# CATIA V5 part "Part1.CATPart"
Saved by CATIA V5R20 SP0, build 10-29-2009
Part number: 饮料瓶
Material "Gravel 1": density 2250 kg/m3, Young's modulus 5e+10 Pa, Poisson ratio 0.25
Bounding box of the stored display mesh (mm): x -25 to 26, y -25 to 180.655, z 0 to 110
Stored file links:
  C:\Users\DELL\Desktop\饮料瓶\Part1.CATPart
  C:\Program Files (x86)\Dassault Systemes\B20\intel_a\startup\materials\Catalog.CATMaterial
  C:\Program Files (x86)\Dassault Systemes\B20\intel_a\startup\materials\kitchen_floor.jpg
  C:\Program Files (x86)\Dassault Systemes\B20\intel_a\startup\materials\gravel_1.jpg
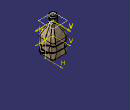
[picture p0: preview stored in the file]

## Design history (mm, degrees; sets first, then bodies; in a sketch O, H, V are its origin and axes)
Set1
  Sketch1 on xy-plane, origin (0, 0, 0), H (1, 0, 0), V (0, 1, 0)
    line L1 (25, 25) -> (25, -25)
    line L2 (25, -25) -> (-25, -25)
    line L3 (-25, -25) -> (-25, 25)
    line L4 (-25, 25) -> (25, 25)
    length L1 = 50
    length L2 = 50
    vertical: L1 V, L3 V
    horizontal: L2 H, L4 H
    equidistance: L1 L3 O, L2 L4 O
  Sketch2 on face of Pad1 from Sketch1.L3, origin (-25, 0, 0), H (0, -1, 0), V (0, 0, 1)
    spline S1 through (-40, 10) (-10, 20) (20, 10) (30, 20) (40, 30)
  Extrude1: Element1 Sketch2, Lim1 80, Lim2 80
  MultiSel1: CommonCtxFeats ({extract ExtractElem face of Pad1 from Sketch1.L3}; {extract ExtractElem face of Fillet1}; {extract ExtractElem face of Pad1 from Sketch1.L2}; {extract ExtractElem face of Fillet1}; {extract ExtractElem face of Pad1 from Sketch1.L1}; {extract ExtractElem face of Fillet1}; {extract ExtractElem face of Pad1 from Sketch1.L4}; {extract ExtractElem face of Fillet1})
  Sketch3 on face of Pad1 from Sketch1.L2, origin (0, -25, 0), H (1, 0, 0), V (0, 0, 1)
    spline S1 through (-30, 30) (-10, 40) (20, 30) (40, 40)
  Extrude2: Element1 Sketch3, Lim1 80, Lim2 80
  Sketch4 on face of Pad1 from Sketch1.L3, origin (-25, 0, 0), H (0, -1, 0), V (0, 0, 1)
    spline S1 through (-40, 30) (-10, 40) (10, 30) (50, 40)
  Extrude3: Element1 Sketch4, Lim1 80, Lim2 80
  MultiSel2: CommonCtxFeats ({extract ExtractElem face of Pad1 from Sketch1.L3}; {extract ExtractElem face of Fillet1}; {extract ExtractElem face of Pad1 from Sketch1.L2}; {extract ExtractElem face of Fillet1}; {extract ExtractElem face of Pad1 from Sketch1.L1}; {extract ExtractElem face of Fillet1}; {extract ExtractElem face of Pad1 from Sketch1.L4}; {extract ExtractElem face of Fillet1})
  Join1: Elements ({intersect ToIntersect1 {extract ExtractElem face of Pad1 from Sketch1.L3}, ToIntersect2 Extrude1}; {intersect ToIntersect1 {extract ExtractElem face of Fillet1}, ToIntersect2 Extrude1}; {intersect ToIntersect1 {extract ExtractElem face of Pad1 from Sketch1.L2}, ToIntersect2 Extrude1}; {intersect ToIntersect1 {extract ExtractElem face of Fillet1}, ToIntersect2 Extrude1}; {intersect ToIntersect1 {extract ExtractElem face of Pad1 from Sketch1.L1}, ToIntersect2 Extrude1}; {intersect ToIntersect1 {extract ExtractElem face of Fillet1}, ToIntersect2 Extrude1}; {intersect ToIntersect1 {extract ExtractElem face of Pad1 from Sketch1.L4}, ToIntersect2 Extrude1}; {intersect ToIntersect1 {extract ExtractElem face of Fillet1}, ToIntersect2 Extrude1})
  Join2: Elements ({intersect ToIntersect1 {extract ExtractElem face of Pad1 from Sketch1.L3}, ToIntersect2 Extrude3}; {intersect ToIntersect1 {extract ExtractElem face of Fillet1}, ToIntersect2 Extrude3}; {intersect ToIntersect1 {extract ExtractElem face of Pad1 from Sketch1.L2}, ToIntersect2 Extrude3}; {intersect ToIntersect1 {extract ExtractElem face of Fillet1}, ToIntersect2 Extrude3}; {intersect ToIntersect1 {extract ExtractElem face of Pad1 from Sketch1.L1}, ToIntersect2 Extrude3}; {intersect ToIntersect1 {extract ExtractElem face of Fillet1}, ToIntersect2 Extrude3}; {intersect ToIntersect1 {extract ExtractElem face of Pad1 from Sketch1.L4}, ToIntersect2 Extrude3}; {intersect ToIntersect1 {extract ExtractElem face of Fillet1}, ToIntersect2 Extrude3})
  Plane1: type Normal, Curve Join1, RefPoint vertex [face of MultiSel1 | face of MultiSel1]
  Circle1: type CtrRad, Start 0, End 180, Center vertex [face of MultiSel1 | face of MultiSel1], Support Plane1, Radius 1, FirstDirection (1, 0, 0)
  Plane2: type Normal, Curve Join2, RefPoint vertex [face of MultiSel2 | face of MultiSel2]
  Circle2: type CtrRad, Start 0, End 180, Center vertex [face of MultiSel2 | face of MultiSel2], Support Plane2, Radius 1, FirstDirection (0, 1, 0)
Body1 (main body), material "Gravel 1"
  Pad1: profile Sketch1, direction (0, 0, 1), length 50
  Fillet1: on edge [face of Pad1 from Sketch1.L2 | face of Pad1 from Sketch1.L3]; edge [face of Pad1 from Sketch1.L3 | face of Pad1 from Sketch1.L4]; edge [face of Pad1 from Sketch1.L4 | face of Pad1 from Sketch1.L1]; edge [face of Pad1 from Sketch1.L1 | face of Pad1 from Sketch1.L2]
  Plane3: type Offset, RefPlane xy-plane, Offset 90
  Sketch5 on Plane3, origin (0, 0, 90), H (1, 0, 0), V (0, 1, 0)
    circle A1 centre (0, 0) radius 10
  Pad2: profile Sketch5, direction (0, 0, 1), length 20
  Fillet2: radius 5, on edge [start face of Pad1 | face of Pad1 from Sketch1.L2]
  Sketch6 on end face of Pad1, origin (0, 0, 50), H (1, 0, 0), V (0, 1, 0)
    point P1 (25, 0)
    distance V P1 = 25
  Sketch7 on Plane3, origin (0, 0, 90), H (1, 0, 0), V (0, 1, 0)
    point P1 (10, 0)
    distance V P1 = 10
    coincidence: P1 H
  Loft1: solid, Sections ({boundary Boundary {extract ExtractElem start face of Pad2}}; {boundary Boundary {extract ExtractElem end face of Pad1}}), StartFace start face of Pad2, EndFace end face of Pad1
  Slot1: profile Circle2, centre curve Join2
  Slot2: profile Circle1, centre curve Join1
  Shell1: IntOffset 1, Face end face of Pad2, ExtOffset 0
  Plane4: type Offset, RefPlane xy-plane, Offset 92
  Sketch8 on Plane4, origin (0, 0, 92), H (1, 0, 0), V (0, 1, 0)
    point P1 (10, 0)
    distance O P1 = 10
    coincidence: P1 H
  Helix1: Direction Z axis, RefPoint Sketch8, Pitch 3, Height 15, TaperAngle 0
  Point1: type OnCurve, Support Helix1, Length 5
  Point2: type OnCurve, Support Helix1, Length 5
  Line1: type PtDir, RefPoint vertex of Helix1, Direction (1, 0, 0), Start 0, End -5
  Line2: type PtDir, RefPoint Sketch8, Direction (1, 0, 0), Start 0, End -5
  Connect1: Curve1 Line2, Point1 vertex of Line2, Tension1 1, Curve2 Helix1, Point2 Point1, Tension2 1
  Connect2: Curve1 Line1, Point1 vertex of Line1, Tension1 1, Curve2 Connect1, Point2 Point2, Tension2 1
  Plane5: type Normal, Curve Connect2, RefPoint vertex of Connect2
  Circle3: type CtrRad, Start 0, End 180, Center vertex of Connect2, Support Plane5, Radius 1, FirstDirection (0, 1, 0)
  Rib1: profile Circle3, centre curve Connect2
  Sketch9 on Plane4, origin (0, 0, 92), H (1, 0, 0), V (0, 1, 0)
    circle A1 centre (0, 0) radius 9
  Pocket1: profile Sketch9, direction (0, 0, 1), length 20
Body2
  Sketch10 on face of Pad1 from Sketch1.L1, origin (25, 0, 0), H (0, 1, 0), V (0, 0, 1)
    polyline C1
    polyline C2
    polyline C3
    polyline C4
    polyline C5
    polyline C6
    polyline C7
    polyline C8
    polyline C9
    polyline C10
    polyline C11
  Sketch11 on face of Pad1 from Sketch1.L1, origin (25, 0, 0), H (0, 1, 0), V (0, 0, 1)
    polyline C1
    polyline C2
    polyline C3
    polyline C4
    polyline C5
    polyline C6
    polyline C7
    polyline C8
    polyline C9
    polyline C10
    polyline C11
  Pad3: profile Sketch11, direction (1, 0, 0), length 1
